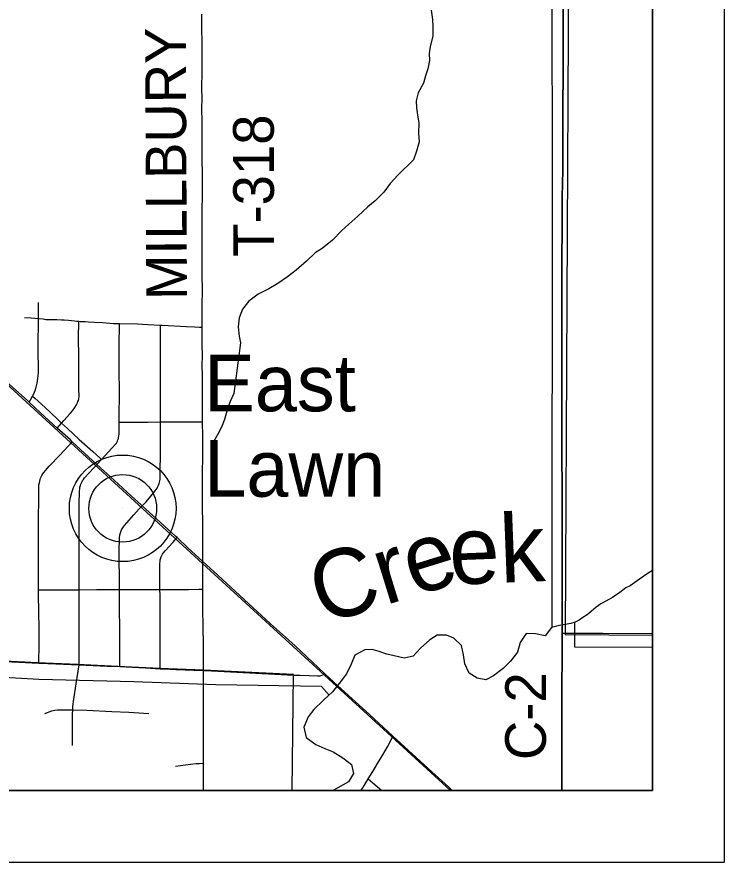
# Model space of a CAD drawing. Extents: x 0 to 40.2, y 0 to 22.
# Drawn here: x 8.013 to 9, y 14 to 15.18 of the extents above; entities that cross this region are included whole.
import ezdxf

# ---------------------------------------------------------------- set-up
doc = ezdxf.new("R2010")
doc.units = 0
for name, color, linetype in [('GM_X_Adjacent_County', 7, 'Continuous'), ('GM_X_Corporation', 7, 'Continuous'), ('GM_X_County_Road_Text', 7, 'Continuous'), ('GM_X_Interchange_Ramps', 7, 'Continuous'), ('GM_X_Major_Lake', 7, 'Continuous'), ('GM_X_Major_Lake_Text', 7, 'Continuous'), ('GM_X_Major_River', 7, 'Continuous'), ('GM_X_Minor_Lake', 7, 'Continuous'), ('GM_X_Minor_River', 7, 'Continuous'), ('GM_X_Rail_Line', 7, 'Continuous'), ('GM_X_Rail_Line_Text', 7, 'Continuous'), ('GM_X_State_Shield', 7, 'Continuous'), ('GM_X_Township_Road', 7, 'Continuous'), ('GM_X_Unincorporated', 7, 'Continuous'), ('GM_X_Unincorporated_Location', 7, 'Continuous'), ('GM_X_US_Shield', 7, 'Continuous')]:
    doc.layers.add(name, color=color, linetype=linetype)

msp = doc.modelspace()

# ---------------------------------------------------------------- linework, layer by layer
at = {"layer": 'GM_X_Adjacent_County'}
for p, q in [((9, 21), (9, 14)), ((8.9, 20.9), (8.9, 14.1)), ((2.1, 14.1), (8.9, 14.1)), ((2, 14), (9, 14))]:
    msp.add_line(p, q, dxfattribs=at)
at = {"layer": 'GM_X_Corporation'}
for points in [[(8.7756, 15.208), (8.7754, 15.1708), (8.7753, 15.1086), (8.775, 15.0465), (8.7748, 15.0123), (8.7748, 14.9657), (8.7741, 14.9284), (8.7736, 14.7979), (8.7734, 14.7575), (8.7734, 14.6767), (8.7738, 14.5679), (8.7739, 14.5213), (8.7741, 14.4374), (8.7741, 14.3972), (8.774, 14.32), (8.7739, 14.2822), (8.7738, 14.249), (8.7737, 14.2107), (8.7736, 14.1113), (8.7736, 14.1), (8.9, 14.1), (8.9, 17.4415)], [(8.7756, 15.208), (8.7754, 15.1708), (8.7753, 15.1086), (8.775, 15.0465), (8.7748, 15.0123), (8.7748, 14.9657), (8.7741, 14.9284), (8.7736, 14.7979), (8.7734, 14.7575), (8.7734, 14.6767), (8.7738, 14.5679), (8.7739, 14.5213), (8.7741, 14.4374), (8.7741, 14.3972), (8.774, 14.32), (8.7739, 14.2822), (8.7738, 14.249), (8.7737, 14.2107), (8.7736, 14.1113), (8.7736, 14.1), (8.9, 14.1), (8.9, 17.4415)], [(2.1, 14.1), (8.7736, 14.1), (8.7736, 14.1113), (8.7737, 14.2107), (8.7738, 14.249), (8.7739, 14.2822), (8.774, 14.32), (8.7741, 14.3972), (8.7741, 14.4374), (8.7739, 14.5213), (8.7738, 14.5679), (8.7734, 14.6767), (8.7734, 14.7575), (8.7736, 14.7979), (8.7741, 14.9284), (8.7748, 14.9657), (8.7748, 15.0123), (8.775, 15.0465), (8.7753, 15.1086), (8.7754, 15.1708), (8.7756, 15.208)], [(2.9469, 14.1), (8.7736, 14.1), (8.7736, 14.1113), (8.7737, 14.2107), (8.7738, 14.249), (8.7739, 14.2822), (8.774, 14.32), (8.7741, 14.3972), (8.7741, 14.4374), (8.7739, 14.5213), (8.7738, 14.5679), (8.7734, 14.6767), (8.7734, 14.7575), (8.7736, 14.7979), (8.7741, 14.9284), (8.7748, 14.9657), (8.7748, 15.0123), (8.775, 15.0465), (8.7753, 15.1086), (8.7754, 15.1708), (8.7756, 15.208)]]:
    msp.add_lwpolyline(points, dxfattribs=at)
for points in [[(8.9, 14.3168), (8.9, 15.3312), (8.7824, 15.3322), (8.7827, 15.2522), (8.7784, 14.3178)], [(7.7701, 14.1), (8.3972, 14.1), (8.3994, 14.2616), (8.2735, 14.2679), (8.2129, 14.2704), (8.1543, 14.2731), (8.0979, 14.2756), (8.0423, 14.2781), (7.9407, 14.2831), (7.7704, 14.2911)]]:
    msp.add_lwpolyline(points, close=True, dxfattribs=at)
at = {"layer": 'GM_X_Interchange_Ramps'}
msp.add_lwpolyline([(8.9, 14.4071), (8.8942, 14.4031), (8.8821, 14.3951), (8.8688, 14.3856), (8.8631, 14.3826), (8.8547, 14.3761), (8.8441, 14.3693), (8.835, 14.3643), (8.8282, 14.3605), (8.8217, 14.356), (8.8145, 14.3499), (8.8088, 14.345), (8.8031, 14.3415), (8.7978, 14.3377), (8.7921, 14.3347), (8.7864, 14.3332), (8.7733, 14.3309)], dxfattribs=at)
at = {"layer": 'GM_X_Major_Lake'}
for points in [[(8.0305, 14.6418), (8.0285, 14.6437), (7.9907, 14.6779), (7.9651, 14.7015), (7.931, 14.7324), (7.8741, 14.7844), (7.8472, 14.8094), (7.8266, 14.8283), (7.8043, 14.8491), (7.7898, 14.8626), (7.7734, 14.8777), (7.7701, 14.8808)], [(8.6206, 14.1), (8.6153, 14.1049), (8.5924, 14.126), (8.538, 14.1757), (8.5052, 14.2058), (8.4612, 14.2462), (8.4436, 14.2624), (8.442, 14.2639), (8.4014, 14.3016), (8.3881, 14.3137), (8.3673, 14.3325), (8.3303, 14.3667), (8.2938, 14.4005), (8.2727, 14.4194), (8.2671, 14.4246), (8.2525, 14.4381), (8.2368, 14.4528), (8.2352, 14.4542), (8.2131, 14.4742), (8.188, 14.4973), (8.1866, 14.4987), (8.1733, 14.5109), (8.149, 14.5331), (8.1251, 14.5551), (8.0907, 14.5867), (8.0881, 14.5891), (8.0696, 14.6057), (8.0461, 14.6271), (8.0305, 14.6418)]]:
    msp.add_lwpolyline(points, dxfattribs=at)
at = {"layer": 'GM_X_Major_Lake_Text'}
for points in [[(8.7742, 14.3195), (8.7743, 14.3966), (8.7743, 14.4369), (8.7741, 14.5208), (8.774, 14.5674), (8.7736, 14.6761), (8.7736, 14.7569), (8.7738, 14.7973), (8.7743, 14.9279), (8.775, 14.9651), (8.775, 15.0117), (8.7753, 15.0459), (8.7755, 15.1081), (8.7757, 15.1702), (8.7758, 15.2075), (8.7754, 15.2446)], [(8.7738, 14.1), (8.7739, 14.1107), (8.7739, 14.2102), (8.774, 14.2484), (8.7741, 14.2816), (8.7742, 14.3195)]]:
    msp.add_lwpolyline(points, dxfattribs=at)
at = {"layer": 'GM_X_Major_River'}
msp.add_lwpolyline([(4.9799, 17.4209), (5.3025, 17.1358), (5.9504, 16.5554), (6.6271, 15.9327), (7.157, 15.4476), (7.7681, 14.8787), (8.2449, 14.4419), (8.6184, 14.1)], dxfattribs=at)
at = {"layer": 'GM_X_Minor_Lake'}
msp.add_line((8.9, 14.2994), (8.7917, 14.2998), dxfattribs=at)
for points in [[(8.7591, 15.8558), (8.7582, 15.7275), (8.7599, 15.5708), (8.7596, 15.3648), (8.7601, 15.3257), (8.7596, 15.1925), (8.7603, 14.9751), (8.76, 14.7642), (8.7595, 14.5433), (8.7595, 14.3285)], [(8.5915, 15.1892), (8.5932, 15.1759), (8.5938, 15.1664), (8.5936, 15.1527), (8.59, 15.1384), (8.5887, 15.1285), (8.5889, 15.1187), (8.5865, 15.1073), (8.5836, 15.0975), (8.5805, 15.0869), (8.5734, 15.0737), (8.5706, 15.0624), (8.5708, 15.0529), (8.5722, 15.043), (8.5739, 15.0312), (8.5737, 15.0172), (8.5746, 15.0054), (8.571, 14.9922), (8.5667, 14.9801), (8.5448, 14.9589), (8.534, 14.9473), (8.5251, 14.9349), (8.5132, 14.9229), (8.5032, 14.9144), (8.489, 14.9013), (8.4763, 14.8905), (8.4664, 14.8812), (8.4537, 14.8681), (8.4391, 14.8562), (8.4296, 14.8503), (8.4173, 14.8387), (8.4031, 14.8261), (8.3908, 14.8168), (8.3774, 14.8075), (8.3648, 14.8001), (8.35, 14.7928), (8.3369, 14.7827), (8.3281, 14.7715), (8.3233, 14.7594), (8.322, 14.7469), (8.3233, 14.734), (8.3254, 14.7245), (8.316, 14.654), (8.3109, 14.6427), (8.3069, 14.6314), (8.3029, 14.6175), (8.2986, 14.6069), (8.2939, 14.5971), (8.2877, 14.5866)], [(8.7917, 14.2998), (8.7918, 14.3346)], [(8.7724, 14.3306), (8.7591, 14.3274), (8.7506, 14.3158), (8.7371, 14.3186), (8.7238, 14.3189), (8.7157, 14.3065), (8.7117, 14.2929), (8.702, 14.2805), (8.6917, 14.2704), (8.6783, 14.26), (8.6676, 14.2545), (8.6555, 14.2566), (8.6443, 14.2636), (8.6384, 14.2766), (8.6363, 14.2891), (8.6335, 14.3025), (8.6231, 14.3125), (8.6129, 14.3165), (8.5997, 14.3167), (8.5894, 14.31), (8.5763, 14.2985), (8.566, 14.2872), (8.5538, 14.2844), (8.5399, 14.2877), (8.5293, 14.2901), (8.5188, 14.2941), (8.509, 14.2965), (8.4988, 14.2963), (8.485, 14.2889), (8.4799, 14.2761), (8.4733, 14.2629), (8.4632, 14.2494), (8.4536, 14.2374), (8.4413, 14.2259), (8.4275, 14.2128), (8.4197, 14.2027), (8.4138, 14.1884), (8.417, 14.1739), (8.4305, 14.1642), (8.4429, 14.1587), (8.4545, 14.1539), (8.468, 14.1457), (8.48, 14.1364), (8.4828, 14.1235), (8.4758, 14.1118), (8.4613, 14.1037), (8.4542, 14.1)], [(8.4489, 14.233), (8.4382, 14.2449), (8.2911, 14.2473), (8.1765, 14.2514), (8.0441, 14.2547), (7.9221, 14.2616)]]:
    msp.add_lwpolyline(points, dxfattribs=at)
at = {"layer": 'GM_X_Rail_Line'}
msp.add_line((8.1251, 14.5551), (8.1316, 14.562), dxfattribs=at)
for points in [[(8.2719, 14.7466), (8.2719, 14.7589), (8.272, 14.775), (8.2721, 14.7999), (8.2719, 14.818), (8.2719, 14.8434), (8.2718, 14.882), (8.2719, 14.9031), (8.2722, 14.9372), (8.2721, 14.9503), (8.2718, 14.9907), (8.2717, 15.0054), (8.2718, 15.0297), (8.2715, 15.0552), (8.2717, 15.0626), (8.2716, 15.0832), (8.2717, 15.1), (8.2718, 15.1161), (8.2718, 15.136), (8.2713, 15.1715), (8.2712, 15.1833)], [(8.0435, 14.7587), (8.0436, 14.7667), (8.0434, 14.7808)], [(8.0242, 14.76), (8.0334, 14.7596), (8.0435, 14.7587)], [(8.0352, 14.6503), (8.0369, 14.6535), (8.0387, 14.6581), (8.0402, 14.6629), (8.0416, 14.6684), (8.0427, 14.6749), (8.0431, 14.6786), (8.0435, 14.6831), (8.0434, 14.6923), (8.0432, 14.7094), (8.0431, 14.7186), (8.0435, 14.7587)], [(8.0435, 14.7587), (8.0499, 14.7581), (8.0538, 14.7575), (8.0589, 14.7573), (8.069, 14.7571), (8.0754, 14.7567), (8.0793, 14.7566), (8.0853, 14.7562), (8.0938, 14.7554), (8.0968, 14.7551), (8.0999, 14.7549)], [(8.0757, 14.6128), (8.0789, 14.6165), (8.0876, 14.6261), (8.0908, 14.63), (8.094, 14.6346), (8.0963, 14.6381), (8.0977, 14.6408), (8.0985, 14.6427), (8.0991, 14.6444), (8.0996, 14.6465), (8.1001, 14.6502), (8.1001, 14.6536), (8.1, 14.6569), (8.0998, 14.6628), (8.0998, 14.6746), (8.0998, 14.6781), (8.0998, 14.6835), (8.0998, 14.6878), (8.0997, 14.6984), (8.0996, 14.7115), (8.0994, 14.7253), (8.0993, 14.7301), (8.0993, 14.738), (8.0997, 14.7478), (8.0999, 14.7549)], [(8.0999, 14.7549), (8.1018, 14.7547), (8.1084, 14.7544), (8.1132, 14.7541), (8.1217, 14.7536), (8.1328, 14.753), (8.1482, 14.7519), (8.1567, 14.7517)], [(8.1561, 14.6141), (8.1563, 14.6623), (8.1562, 14.681), (8.1562, 14.7232), (8.1567, 14.7483), (8.1567, 14.7517)], [(8.1567, 14.7517), (8.1816, 14.7511), (8.1958, 14.7502), (8.2136, 14.7493)], [(8.2136, 14.6143), (8.2135, 14.6206), (8.2138, 14.6795), (8.2139, 14.7179), (8.2136, 14.746), (8.2136, 14.7493)], [(8.2136, 14.7493), (8.216, 14.7492), (8.2501, 14.7476), (8.2611, 14.7472), (8.2679, 14.7468), (8.2719, 14.7466)], [(8.2725, 14.6143), (8.2725, 14.6374), (8.2725, 14.6399), (8.2723, 14.6565), (8.2721, 14.6602), (8.2722, 14.6794), (8.272, 14.6931), (8.2721, 14.7068), (8.272, 14.7223), (8.2719, 14.7466)], [(8.0305, 14.6418), (8.0323, 14.6451), (8.0352, 14.6503)], [(8.0352, 14.6503), (8.0386, 14.6473), (8.0478, 14.6391), (8.0591, 14.6285), (8.0713, 14.617), (8.0757, 14.6128)], [(8.0696, 14.6057), (8.0729, 14.6095), (8.0757, 14.6128)], [(8.0757, 14.6128), (8.084, 14.605), (8.1004, 14.5898), (8.1195, 14.573), (8.1292, 14.5642), (8.1316, 14.562)], [(8.1316, 14.562), (8.1511, 14.5831), (8.1522, 14.5849), (8.1536, 14.5877), (8.1544, 14.5894), (8.155, 14.5912), (8.1553, 14.5928), (8.1557, 14.5945), (8.1559, 14.5971), (8.156, 14.599), (8.156, 14.6009), (8.1561, 14.6141)], [(8.1561, 14.6141), (8.1615, 14.6141), (8.1795, 14.6138), (8.1963, 14.6142), (8.2136, 14.6143)], [(8.188, 14.4973), (8.1935, 14.5028), (8.2003, 14.5108), (8.2063, 14.518), (8.2076, 14.5199), (8.2089, 14.5219), (8.2102, 14.5243), (8.211, 14.5261), (8.2118, 14.5282), (8.2124, 14.5303), (8.2129, 14.5319), (8.2131, 14.5339), (8.2133, 14.5357), (8.2134, 14.5383), (8.2136, 14.5768), (8.2136, 14.6143)], [(8.2136, 14.6143), (8.2155, 14.6143), (8.2435, 14.6146), (8.2657, 14.6144), (8.2725, 14.6143)], [(8.2727, 14.4194), (8.2728, 14.425), (8.2727, 14.431), (8.273, 14.4522), (8.2727, 14.474), (8.2725, 14.4951), (8.2724, 14.497), (8.2724, 14.5013), (8.2724, 14.5069), (8.2725, 14.5187), (8.2725, 14.5261), (8.2723, 14.5348), (8.2723, 14.5392), (8.2725, 14.5503), (8.2726, 14.5585), (8.2726, 14.5715), (8.2726, 14.5752), (8.2726, 14.5821), (8.2726, 14.5908), (8.2726, 14.6013), (8.2725, 14.6069), (8.2725, 14.6082), (8.2725, 14.6143)], [(8.0437, 14.3799), (8.0435, 14.3977), (8.0436, 14.4221), (8.0435, 14.4344), (8.0436, 14.4648), (8.0439, 14.5213), (8.044, 14.5245), (8.0442, 14.5265), (8.0447, 14.5295), (8.0452, 14.5317), (8.0457, 14.5338), (8.0462, 14.5356), (8.0471, 14.5376), (8.0481, 14.5397), (8.0495, 14.542), (8.0509, 14.5439), (8.0586, 14.5525), (8.0731, 14.5679), (8.085, 14.5806), (8.0907, 14.5867)], [(8.1001, 14.3802), (8.1001, 14.4189), (8.1004, 14.442), (8.1004, 14.5015), (8.1008, 14.5158), (8.1014, 14.5233), (8.1019, 14.5255), (8.1025, 14.5276), (8.1033, 14.5295), (8.1042, 14.5312), (8.1051, 14.5327), (8.1061, 14.534), (8.1078, 14.5361), (8.1207, 14.5503), (8.1251, 14.5551)], [(8.1564, 14.3806), (8.1564, 14.3849), (8.1559, 14.4339), (8.1565, 14.4523), (8.1567, 14.4542), (8.1569, 14.4555), (8.1571, 14.4568), (8.1574, 14.4581), (8.1578, 14.4595), (8.1583, 14.4608), (8.1589, 14.4622), (8.1595, 14.4635), (8.1602, 14.4649), (8.1611, 14.4666), (8.1621, 14.4681), (8.1633, 14.4697), (8.1764, 14.4847), (8.1838, 14.493), (8.188, 14.4973)], [(8.213, 14.3805), (8.2128, 14.4066), (8.2129, 14.4165), (8.2131, 14.4202), (8.2134, 14.4218), (8.2138, 14.4233), (8.2142, 14.4247), (8.2148, 14.4262), (8.2156, 14.4279), (8.2166, 14.4296), (8.2176, 14.431), (8.2207, 14.4349), (8.2307, 14.446), (8.2368, 14.4528)], [(8.2728, 14.3809), (8.2726, 14.4088), (8.2727, 14.4194)], [(8.0437, 14.3799), (8.0488, 14.3798), (8.0605, 14.3798), (8.0667, 14.3801), (8.089, 14.3802), (8.1001, 14.3802)], [(8.044, 14.2777), (8.0441, 14.2847), (8.0444, 14.2977), (8.0445, 14.3288), (8.0442, 14.3462), (8.0437, 14.3762), (8.0437, 14.3799)], [(8.1001, 14.3802), (8.1244, 14.3803), (8.1393, 14.3804), (8.1511, 14.3805), (8.1564, 14.3806)], [(8.1002, 14.2752), (8.1002, 14.2798), (8.1001, 14.3313), (8.1001, 14.3802)], [(8.1564, 14.3806), (8.1598, 14.3806), (8.2113, 14.3805), (8.213, 14.3805)], [(8.1569, 14.2728), (8.157, 14.2782), (8.157, 14.3123), (8.1565, 14.3669), (8.1564, 14.3806)], [(8.213, 14.3805), (8.2529, 14.3806), (8.2672, 14.3808), (8.2728, 14.3809)], [(8.2131, 14.2699), (8.2131, 14.2757), (8.2133, 14.2906), (8.2133, 14.2974), (8.2132, 14.3513), (8.2131, 14.3724), (8.213, 14.3805)], [(8.2737, 14.2673), (8.2735, 14.3), (8.2735, 14.3087), (8.2732, 14.323), (8.2731, 14.3311), (8.2732, 14.336), (8.273, 14.346), (8.2728, 14.3648), (8.273, 14.3721), (8.2728, 14.3809)], [(8.7742, 14.3195), (8.8309, 14.3196), (8.9, 14.3192)], [(7.7709, 14.2909), (7.8117, 14.2887), (7.8322, 14.2877), (7.8645, 14.2862), (7.9042, 14.2845), (7.9409, 14.2825), (7.9781, 14.2807), (8.044, 14.2777)], [(8.044, 14.2777), (8.0564, 14.2771), (8.1002, 14.2752)], [(8.1002, 14.2752), (8.1395, 14.2735), (8.1569, 14.2728)], [(8.1569, 14.2728), (8.1655, 14.2724), (8.1928, 14.2709), (8.2131, 14.2699)], [(8.2131, 14.2699), (8.2189, 14.2695), (8.2351, 14.269), (8.2737, 14.2673)], [(8.2739, 14.1381), (8.2737, 14.1683), (8.2737, 14.1938), (8.2736, 14.2211), (8.2737, 14.2628), (8.2737, 14.2673)], [(8.2737, 14.2673), (8.2847, 14.2668), (8.3201, 14.265), (8.3996, 14.2611)], [(8.3996, 14.2611), (8.4082, 14.2607), (8.4212, 14.2602), (8.4329, 14.2599), (8.4349, 14.26), (8.4361, 14.2601), (8.4375, 14.2606), (8.4436, 14.2624)], [(8.5033, 14.1162), (8.5098, 14.1265), (8.5165, 14.1377), (8.5238, 14.1497), (8.5302, 14.161), (8.5344, 14.169), (8.538, 14.1757)], [(8.2739, 14.1), (8.2738, 14.1036), (8.2739, 14.1353), (8.2739, 14.1381)], [(8.4934, 14.1), (8.4936, 14.1002), (8.4946, 14.1016), (8.4959, 14.1035), (8.4981, 14.1074), (8.5033, 14.1162)], [(8.5033, 14.1162), (8.51, 14.1105), (8.5224, 14.1)]]:
    msp.add_lwpolyline(points, dxfattribs=at)
at = {"layer": 'GM_X_State_Shield'}
msp.add_line((8.161, 14.4937), (8.161, 14.4937), dxfattribs=at)
at = {"layer": 'GM_X_Township_Road'}
msp.add_lwpolyline([(2.1, 20.9), (8.9, 20.9), (8.9, 14.1), (2.1, 14.1)], close=True, dxfattribs=at)
at = {"layer": 'GM_X_Unincorporated'}
for radius in [0.0744, 0.0472]:
    msp.add_circle((8.161, 14.4937), radius, dxfattribs=at)
at = {"layer": 'GM_X_Unincorporated_Location'}
for points in [[(8.091, 14.1625), (8.0908, 14.1916), (8.091, 14.2065), (8.0914, 14.2124), (8.0916, 14.217), (8.0929, 14.2274), (8.096, 14.2489), (8.1002, 14.2752)], [(8.0525, 14.2074), (8.062, 14.2109), (8.0641, 14.2115), (8.0663, 14.2119), (8.0699, 14.2124), (8.0743, 14.2127), (8.0842, 14.2126), (8.0914, 14.2124), (8.1109, 14.2119), (8.1457, 14.2103), (8.1693, 14.2092), (8.1976, 14.2073)], [(8.2346, 14.134), (8.2556, 14.1365), (8.2636, 14.1374), (8.2679, 14.1377), (8.2739, 14.1381)]]:
    msp.add_lwpolyline(points, dxfattribs=at)

# ---------------------------------------------------------------- texts
at = {"layer": 'GM_X_County_Road_Text'}
for s, rotation, p in [('MILLBURY', 90.2636, (8.2507, 14.7847)), ('T-318', 90.1295, (8.3722, 14.8449))]:
    msp.add_text(s, height=0.05682, rotation=rotation, dxfattribs=at).set_placement(p)
at = {"layer": 'GM_X_Minor_River'}
for s, rotation, p in [('ek', 2.1966, (8.6179, 14.3871)), ('Cre', 17.1996, (8.4395, 14.3311))]:
    msp.add_text(s, height=0.09476, rotation=rotation, dxfattribs=at).set_placement(p)
at = {"layer": 'GM_X_Rail_Line_Text'}
msp.add_text('C-2', height=0.05682, rotation=89.907, dxfattribs=at).set_placement((8.7514, 14.1424))
at = {"layer": 'GM_X_US_Shield'}
for s, p in [('East', (8.2748, 14.6291)), ('Lawn', (8.2748, 14.5099))]:
    msp.add_text(s, height=0.07898, rotation=0, dxfattribs=at).set_placement(p)

doc.saveas('drawing.dxf')
